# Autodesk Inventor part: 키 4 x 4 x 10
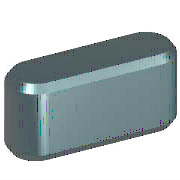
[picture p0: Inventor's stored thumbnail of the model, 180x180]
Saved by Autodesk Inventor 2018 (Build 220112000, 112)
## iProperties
IsCustomPart: 1
Created: 2012-02
Part Number: 키 4 x 4 x 10
Material: 강철, 연강
Description: 키 및 해당 키홈
Document SubType Name: Modeling
Standard: KS B 1311
Designer: mduedu
Standards Organization: KS
Language: ko-KR
Size Designation: 4 x 4 x 10
Categories: <MemberInstance><Categories><Category DisplayName="샤프트 부품" InternalName="7f7aeb1f-a693-4053-b835-cee3144e0d98" Mnemonic="SHFT"><Category DisplayName="키" Interna
Density: 1 g/cm^3
Appearance: 노란색
Author: mduedu
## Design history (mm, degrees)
workplane "Work Plane1"
workplane "Work Plane2"
sketch "스케치1"
  geometry: L1 (2, 2)-(8, 2); L2 (8, -2)-(2, -2); L3 (0, 9.4)-(0, -7.4) reference; L4 (-5, 0)-(30, 0) reference; L5 (10, 0)-(10, 7); A1 r 2 centre (2, 0) between (2, 2) and (2, -2); A2 r 2 centre (8, 0) between (8, -2) and (8, 2)
  constraints: 6 end point, 5 point on circle, 4 tangent, 3 point on line, 2 centre point, 1 horizontal, 1 parallel, 1 perpendicular
  dimensions: "d0" = 2 radius of A1 (= 0.5 x PB); "d13" = 2 radius of A2 (= 0.5 x PB); "d14" = 10 distance between parallel lines of L5 L3 (= NLG)
extrude "본체1" new body sketch "스케치1" taper "d3" = 0 deg; stored distance "d4" = 10
workplane "Work Plane3"
body "Solid1"
chamfer "모따기1" distance "d8" = 0.25 (= PHH); stored, may be unused: second distance "d9" = 0.25 (= PHH), angle "d15" = 45 deg
other parameters: "d1" = -2.5 (= -PNT), "d2" = 1.5 (= PH - PNT), "NLG" = 10 [user parameter; used in 3 equation terms], "PB" = 4 [user parameter; used in 2 equation terms], "PNT" = 2.5 [user parameter; used in 2 equation terms], "PH" = 4 [user parameter; used in 1 equation term], "PHH" = 0.25 [user parameter; used in 2 equation terms], "d10" = 0, "d16" = 0, "d17" = 0, "d18" = 0, "WDMAX" = 12 [user parameter], "RR" = 0.08 [user parameter], "PUEB" = 1.8 [user parameter]
